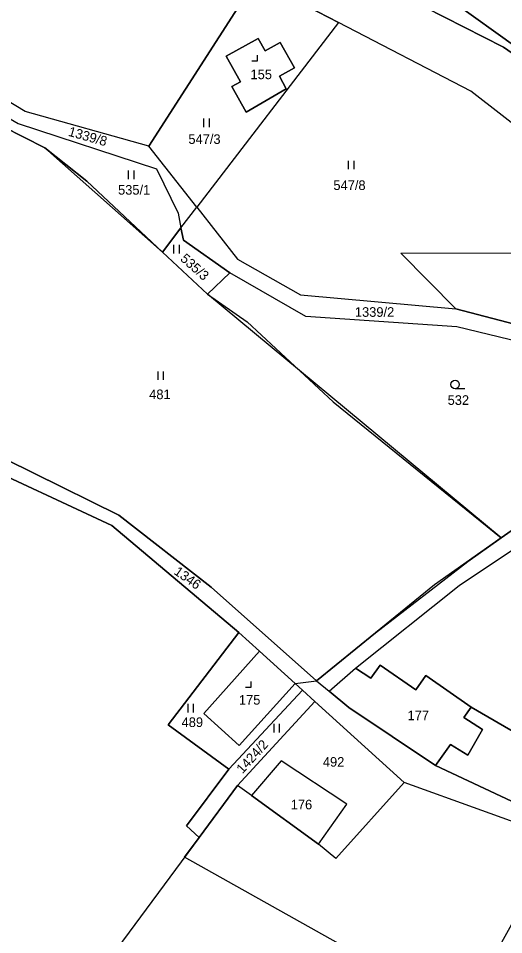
# Model space of a CAD drawing. Extents: x -588699 to -585793, y -1060280 to -1056731.
# Drawn here: x -586660.9 to -586575.1, y -1058797.6 to -1058635.6 of the extents above; entities that cross this region are included whole.
import ezdxf

# ---------------------------------------------------------------- set-up
doc = ezdxf.new("R2010")
doc.units = 0
for name, color, linetype in [('Druh pozemku', 7, 'Continuous'), ('Lesy', 7, 'Continuous'), ('Parcela nároku', 7, 'Continuous')]:
    doc.layers.add(name, color=color, linetype=linetype)

msp = doc.modelspace()

# ---------------------------------------------------------------- linework, layer by layer
at = {"layer": 'Druh pozemku'}
for p, q in [((-586628.17, -1058653.35), (-586628.17, -1058654.85)), ((-586627.15, -1058654.85), (-586627.15, -1058653.35)), ((-586602.61, -1058660.8), (-586602.61, -1058662.3)), ((-586601.58, -1058662.3), (-586601.58, -1058660.8)), ((-586641.49, -1058662.53), (-586641.49, -1058664.03)), ((-586640.46, -1058664.03), (-586640.46, -1058662.53)), ((-586633.47, -1058675.67), (-586633.47, -1058677.17)), ((-586632.45, -1058677.17), (-586632.45, -1058675.67)), ((-586636.28, -1058698.03), (-586636.28, -1058699.53)), ((-586635.26, -1058699.53), (-586635.26, -1058698.03)), ((-586581.98, -1058701.12), (-586583.73, -1058701.12)), ((-586630.98, -1058756.84), (-586630.98, -1058758.34)), ((-586629.95, -1058758.34), (-586629.95, -1058756.84)), ((-586615.78, -1058760.36), (-586615.78, -1058761.86)), ((-586614.76, -1058761.86), (-586614.76, -1058760.36))]:
    msp.add_line(p, q, dxfattribs=at)
for points in [[(-586619.64, -1058643.12), (-586618.64, -1058643.12), (-586618.64, -1058642.12)], [(-586620.75, -1058753.87), (-586619.75, -1058753.87), (-586619.75, -1058752.87)]]:
    msp.add_lwpolyline(points, dxfattribs=at)
msp.add_circle((-586583.73, -1058700.37), 0.75, dxfattribs=at)
at = {"layer": 'Lesy'}
for p, q in [((-586656.24, -1058658.5), (-586667.41, -1058652.83)), ((-586635.45, -1058676.95), (-586656.24, -1058658.5)), ((-586627.51, -1058684.38), (-586635.45, -1058676.95)), ((-586575.6, -1058727.47), (-586627.51, -1058684.38)), ((-586581.47, -1058731.64), (-586575.6, -1058727.47)), ((-586597.79, -1058744.28), (-586581.47, -1058731.64)), ((-586634.46, -1058760.51), (-586621.92, -1058744.2)), ((-586621.92, -1058744.2), (-586618.28, -1058747.51)), ((-586608.24, -1058752.75), (-586597.79, -1058744.28)), ((-586618.28, -1058747.51), (-586611.98, -1058753.23)), ((-586611.98, -1058753.23), (-586608.24, -1058752.75)), ((-586623.71, -1058768.4), (-586634.46, -1058760.51)), ((-586631.19, -1058778.4), (-586623.71, -1058768.4)), ((-586628.98, -1058780.48), (-586631.19, -1058778.4)), ((-586631.56, -1058783.96), (-586628.98, -1058780.48)), ((-586582.39, -1058811.42), (-586631.56, -1058783.96))]:
    msp.add_line(p, q, dxfattribs=at)
at = {"layer": 'Parcela nároku'}
for points in [[(-586597.95, -1058625.16), (-586584.01, -1058632.77), (-586561.96, -1058648.55), (-586562.62, -1058649.44), (-586575.18, -1058640.72), (-586602.99, -1058626.52), (-586665.54, -1058591.33), (-586664.46, -1058588.32), (-586623.04, -1058611.28), (-586607.59, -1058619.84), (-586605.96, -1058620.74), (-586600.89, -1058623.54)], [(-586681.54, -1058639.09), (-586660.99, -1058605.82), (-586618.94, -1058628.76), (-586637.88, -1058658.21), (-586659.72, -1058652.09), (-586665.04, -1058648.92)], [(-586546.79, -1058660.66), (-586542.78, -1058655.4), (-586558.23, -1058643.56), (-586561.96, -1058648.55), (-586584.01, -1058632.77), (-586597.95, -1058625.16), (-586600.89, -1058623.54), (-586599.59, -1058622.65), (-586599.28, -1058622.47), (-586597.4, -1058621.75), (-586595.42, -1058621.47), (-586586.5, -1058620.91), (-586577.55, -1058620.34), (-586574.63, -1058619.84), (-586571.82, -1058618.84), (-586569.97, -1058617.96), (-586565.57, -1058620.73), (-586521.47, -1058658.28), (-586528.54, -1058675.42), (-586531.47, -1058673.53)], [(-586637.88, -1058658.21), (-586618.94, -1058628.76), (-586604.33, -1058636.33), (-586629.39, -1058669.03)], [(-586604.33, -1058636.33), (-586629.39, -1058669.03), (-586622.19, -1058678.18), (-586611.05, -1058684.49), (-586583.61, -1058687), (-586593.33, -1058677.12), (-586569.93, -1058677.07), (-586560.64, -1058666.75), (-586559.3, -1058665.26), (-586580.93, -1058648.48)], [(-586624.19, -1058642.33), (-586618.52, -1058639.16), (-586617.3, -1058641.35), (-586614.64, -1058639.86), (-586612.12, -1058644.37), (-586614.78, -1058645.86), (-586613.55, -1058648.07), (-586620.66, -1058652.23), (-586623.19, -1058647.69), (-586621.67, -1058646.85)], [(-586614.78, -1058645.86), (-586612.12, -1058644.37), (-586614.64, -1058639.86), (-586617.3, -1058641.35), (-586618.52, -1058639.16), (-586624.19, -1058642.33), (-586621.67, -1058646.85), (-586623.19, -1058647.69), (-586620.66, -1058652.23), (-586613.55, -1058648.07)], [(-586656.24, -1058658.5), (-586648.82, -1058664.43), (-586635.45, -1058676.95), (-586627.51, -1058684.38), (-586620.49, -1058689.29), (-586605.29, -1058703.42), (-586575.6, -1058727.47), (-586587.34, -1058735.8), (-586608.24, -1058752.75), (-586626.83, -1058736.19), (-586643.18, -1058723.44), (-586668.27, -1058711.07), (-586694.07, -1058697.8), (-586674.68, -1058649.14), (-586667.41, -1058652.83)], [(-586665.04, -1058648.92), (-586666.36, -1058651.1), (-586660.95, -1058654.23), (-586636.48, -1058662.22), (-586632.69, -1058670.06), (-586632.17, -1058672.66), (-586629.39, -1058669.03), (-586637.88, -1058658.21), (-586659.72, -1058652.09)], [(-586632.69, -1058670.06), (-586632.17, -1058672.66), (-586635.45, -1058676.95), (-586648.82, -1058664.43), (-586656.24, -1058658.5), (-586667.41, -1058652.83), (-586666.36, -1058651.1), (-586660.95, -1058654.23), (-586636.48, -1058662.22)], [(-586629.39, -1058669.03), (-586622.19, -1058678.18), (-586611.05, -1058684.49), (-586583.61, -1058687), (-586541.24, -1058698.07), (-586535.29, -1058700.76), (-586536.03, -1058702.84), (-586537.65, -1058702.32), (-586551.75, -1058697.84), (-586583.39, -1058690.19), (-586610.09, -1058688.31), (-586623.54, -1058680.6), (-586631.72, -1058674.86), (-586632.17, -1058672.66)], [(-586631.72, -1058674.86), (-586623.54, -1058680.6), (-586627.51, -1058684.38), (-586635.45, -1058676.95), (-586632.17, -1058672.66)], [(-586548.16, -1058673.91), (-586542.32, -1058678.44), (-586534.7, -1058687.04), (-586541.24, -1058698.07), (-586583.61, -1058687), (-586593.33, -1058677.12), (-586569.93, -1058677.07), (-586564.47, -1058682.08), (-586563.02, -1058683.41), (-586560.09, -1058680.21), (-586556, -1058675.75), (-586552.61, -1058678.86), (-586550.3, -1058676.3)], [(-586623.54, -1058680.6), (-586627.51, -1058684.38), (-586620.49, -1058689.29), (-586605.29, -1058703.42), (-586575.6, -1058727.47), (-586569.84, -1058723.49), (-586548.56, -1058713.23), (-586551.47, -1058711.11), (-586552.78, -1058712.71), (-586559.44, -1058707.18), (-586551.75, -1058697.84), (-586583.39, -1058690.19), (-586610.09, -1058688.31)], [(-586575.6, -1058727.47), (-586587.34, -1058735.8), (-586608.24, -1058752.75), (-586606, -1058754.58), (-586601.31, -1058750.5), (-586583, -1058735.87), (-586573.59, -1058729.61), (-586568.01, -1058726.38), (-586553.83, -1058719.5), (-586544.49, -1058714.97), (-586534.19, -1058703.6), (-586536.03, -1058702.84), (-586542.94, -1058710.52), (-586548.56, -1058713.23), (-586569.84, -1058723.49)], [(-586583, -1058735.87), (-586573.59, -1058729.61), (-586554.32, -1058744.8), (-586546.76, -1058750.88), (-586558, -1058770.65), (-586580.88, -1058757.4), (-586588.9, -1058751.81), (-586590.67, -1058754.35), (-586596.95, -1058749.97), (-586598.64, -1058752.26), (-586601.31, -1058750.5)], [(-586611.98, -1058753.23), (-586621.86, -1058764.18), (-586628.15, -1058758.51), (-586618.28, -1058747.51), (-586621.92, -1058744.2), (-586634.46, -1058760.51), (-586623.71, -1058768.4), (-586610.69, -1058754.4)], [(-586628.15, -1058758.51), (-586618.28, -1058747.51), (-586611.98, -1058753.23), (-586621.86, -1058764.18)], [(-586590.67, -1058754.35), (-586588.9, -1058751.81), (-586580.88, -1058757.4), (-586582.16, -1058759.24), (-586578.9, -1058761.33), (-586581.45, -1058765.9), (-586584.55, -1058764.03), (-586587.17, -1058767.71), (-586602.48, -1058757.45), (-586606, -1058754.58), (-586601.31, -1058750.5), (-586598.64, -1058752.26), (-586596.95, -1058749.97)], [(-586608.51, -1058756.38), (-586610.69, -1058754.4), (-586623.71, -1058768.4), (-586631.19, -1058778.4), (-586628.98, -1058780.48), (-586622.18, -1058771.27)], [(-586608.51, -1058756.38), (-586592.71, -1058770.73), (-586604.81, -1058784.17), (-586607.85, -1058781.62), (-586602.85, -1058774.59), (-586614.49, -1058766.87), (-586619.73, -1058773.04), (-586622.18, -1058771.27)], [(-586580.88, -1058757.4), (-586558, -1058770.65), (-586564.07, -1058778.59), (-586587.17, -1058767.71), (-586584.55, -1058764.03), (-586581.45, -1058765.9), (-586578.9, -1058761.33), (-586582.16, -1058759.24)], [(-586614.49, -1058766.87), (-586619.73, -1058773.04), (-586607.85, -1058781.62), (-586602.85, -1058774.59)], [(-586628.98, -1058780.48), (-586644.52, -1058801.5), (-586674.36, -1058859.75), (-586676.24, -1058869.35), (-586676.18, -1058876.91), (-586610.33, -1058861.7), (-586565.27, -1058780.61), (-586592.71, -1058770.73), (-586604.81, -1058784.17), (-586607.85, -1058781.62), (-586619.73, -1058773.04), (-586622.18, -1058771.27)]]:
    msp.add_lwpolyline(points, close=True, dxfattribs=at)
for points in [[(-586665.54, -1058591.33), (-586602.99, -1058626.52), (-586575.18, -1058640.72), (-586562.62, -1058649.44), (-586562.02, -1058649.89), (-586562.26, -1058655.2), (-586554.04, -1058661.25), (-586547.94, -1058661.08), (-586547.43, -1058661.49), (-586529.21, -1058677.03), (-586493.41, -1058703.55), (-586488.15, -1058707.45), (-586445.6, -1058736.95), (-586438.6, -1058743.85), (-586431.1, -1058753.5)], [(-586373.84, -1058798.77), (-586399.97, -1058787.16), (-586403.04, -1058785.45), (-586407.1, -1058783.18), (-586411.04, -1058780.99), (-586425.65, -1058772.84), (-586430.27, -1058767.88), (-586439.92, -1058757.51), (-586447.03, -1058749.88), (-586459.59, -1058740.72), (-586472.09, -1058731.41), (-586506.38, -1058706.88), (-586526.71, -1058690.04), (-586530.42, -1058687.01), (-586542.32, -1058678.44), (-586548.16, -1058673.91), (-586559.3, -1058665.26), (-586580.93, -1058648.48), (-586604.33, -1058636.33), (-586618.94, -1058628.76), (-586660.99, -1058605.82)], [(-586668.27, -1058711.07), (-586643.18, -1058723.44), (-586626.83, -1058736.19), (-586608.24, -1058752.75), (-586606, -1058754.58), (-586602.48, -1058757.45), (-586587.17, -1058767.71), (-586564.07, -1058778.59), (-586447.32, -1058823.07), (-586443.51, -1058824.52), (-586443.86, -1058826.94), (-586447.51, -1058825.52), (-586483.01, -1058811.75), (-586495.05, -1058807.2), (-586565.27, -1058780.61), (-586592.71, -1058770.73), (-586608.51, -1058756.38), (-586610.69, -1058754.4), (-586611.98, -1058753.23), (-586618.28, -1058747.51), (-586621.92, -1058744.2), (-586644.38, -1058725.27), (-586669.98, -1058713.39)], [(-586669.98, -1058713.39), (-586644.38, -1058725.27), (-586621.92, -1058744.2), (-586634.46, -1058760.51), (-586623.71, -1058768.4), (-586631.19, -1058778.4), (-586628.98, -1058780.48), (-586644.52, -1058801.5), (-586674.36, -1058859.75)]]:
    msp.add_lwpolyline(points, dxfattribs=at)

# ---------------------------------------------------------------- texts
for s, p in [('155', (-586619.88, -1058646.37)), ('547/3', (-586630.86, -1058657.82)), ('535/1', (-586643.29, -1058666.79)), ('547/8', (-586605.23, -1058665.97)), ('1339/2', (-586601.43, -1058688.39)), ('481', (-586637.79, -1058702.95)), ('532', (-586585.04, -1058703.96)), ('175', (-586621.93, -1058756.97)), ('489', (-586632.06, -1058760.92)), ('177', (-586592.12, -1058759.71)), ('492', (-586607.09, -1058767.94)), ('176', (-586612.77, -1058775.48))]:
    msp.add_text(s, height=1.7, dxfattribs=at).set_placement(p)
for s, rotation, p in [('1339/8', 344.3461, (-586652.21, -1058656.36)), ('535/3', 318.2604, (-586632.42, -1058678.31)), ('1346', 324.8489, (-586633.55, -1058733.78)), ('1424/2', 47.7, (-586621.29, -1058769.27))]:
    msp.add_text(s, height=1.7, rotation=rotation, dxfattribs=at).set_placement(p)

doc.saveas('drawing.dxf')
